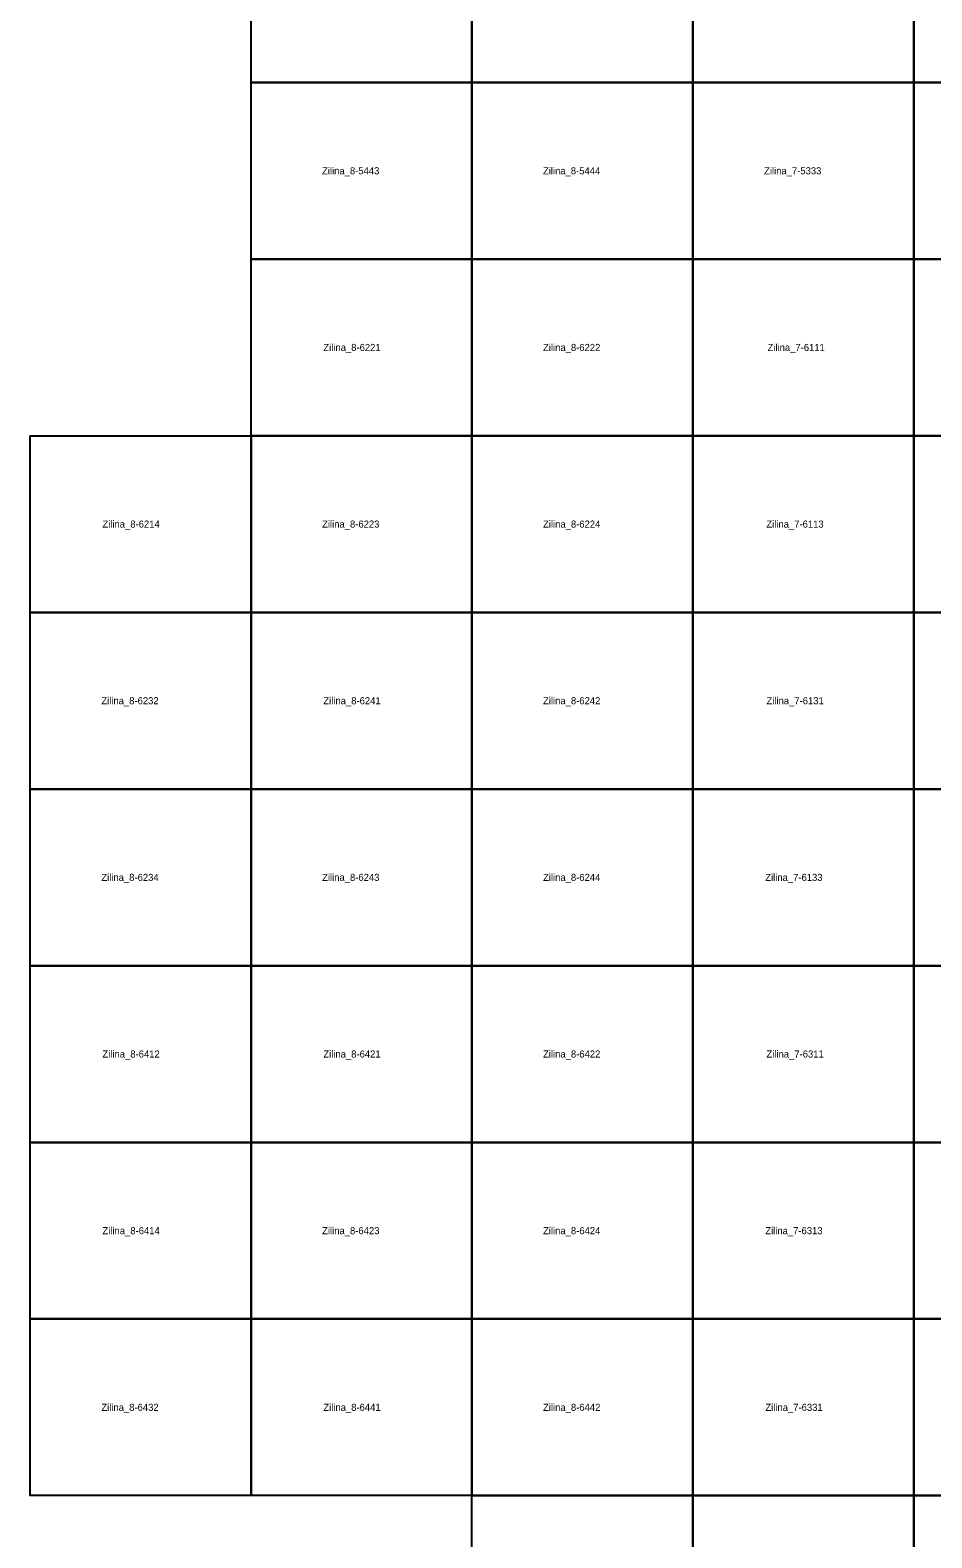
# Model space of a CAD drawing. Extents: x -445938 to -437812, y -1177250 to -1169500.
# Drawn here: x -445938 to -444662, y -1173810 to -1171676 of the extents above; entities that cross this region are included whole.
import ezdxf

# ---------------------------------------------------------------- set-up
doc = ezdxf.new("R2010")
doc.units = 0
for name, color, linetype in [('Vrstva 1', 7, 'Continuous'), ('Vrstva 4', 7, 'Continuous'), ('Vrstva 6', 7, 'Continuous')]:
    doc.layers.add(name, color=color, linetype=linetype)

msp = doc.modelspace()

# ---------------------------------------------------------------- linework, layer by layer
at = {"layer": 'Vrstva 1'}
msp.add_lwpolyline([(-440625, -1175500), (-441562.5, -1175500), (-441562.5, -1175000), (-442812.5, -1175000), (-442812.5, -1175750), (-443437.5, -1175750), (-443437.5, -1177250), (-445000, -1177250), (-445000, -1175500), (-445312.5, -1175500), (-445312.5, -1173750), (-445937.5, -1173750), (-445937.5, -1172250), (-445625, -1172250), (-445625, -1169500), (-444062.5, -1169500), (-444062.5, -1169750), (-441562.5, -1169750), (-441562.5, -1170000), (-440000, -1170000)], dxfattribs=at)
at = {"layer": 'Vrstva 4'}
for points in [[(-445312.5, -1171500), (-445312.5, -1171750), (-445625, -1171750), (-445625, -1171500)], [(-445000, -1171500), (-445000, -1171750), (-445312.5, -1171750), (-445312.5, -1171500)], [(-444687.5, -1171500), (-444687.5, -1171750), (-445000, -1171750), (-445000, -1171500)], [(-444375, -1171500), (-444375, -1171750), (-444687.5, -1171750), (-444687.5, -1171500)], [(-445312.5, -1171750), (-445312.5, -1172000), (-445625, -1172000), (-445625, -1171750)], [(-445000, -1171750), (-445000, -1172000), (-445312.5, -1172000), (-445312.5, -1171750)], [(-444687.5, -1171750), (-444687.5, -1172000), (-445000, -1172000), (-445000, -1171750)], [(-444375, -1171750), (-444375, -1172000), (-444687.5, -1172000), (-444687.5, -1171750)], [(-445312.5, -1172000), (-445312.5, -1172250), (-445625, -1172250), (-445625, -1172000)], [(-445000, -1172000), (-445000, -1172250), (-445312.5, -1172250), (-445312.5, -1172000)], [(-444687.5, -1172000), (-444687.5, -1172250), (-445000, -1172250), (-445000, -1172000)], [(-444375, -1172000), (-444375, -1172250), (-444687.5, -1172250), (-444687.5, -1172000)], [(-445625, -1172250), (-445625, -1172500), (-445937.5, -1172500), (-445937.5, -1172250)], [(-445312.5, -1172250), (-445312.5, -1172500), (-445625, -1172500), (-445625, -1172250)], [(-445000, -1172250), (-445000, -1172500), (-445312.5, -1172500), (-445312.5, -1172250)], [(-444687.5, -1172250), (-444687.5, -1172500), (-445000, -1172500), (-445000, -1172250)], [(-444375, -1172250), (-444375, -1172500), (-444687.5, -1172500), (-444687.5, -1172250)], [(-445625, -1172500), (-445625, -1172750), (-445937.5, -1172750), (-445937.5, -1172500)], [(-445312.5, -1172500), (-445312.5, -1172750), (-445625, -1172750), (-445625, -1172500)], [(-445000, -1172500), (-445000, -1172750), (-445312.5, -1172750), (-445312.5, -1172500)], [(-444687.5, -1172500), (-444687.5, -1172750), (-445000, -1172750), (-445000, -1172500)], [(-444375, -1172500), (-444375, -1172750), (-444687.5, -1172750), (-444687.5, -1172500)], [(-445625, -1172750), (-445625, -1173000), (-445937.5, -1173000), (-445937.5, -1172750)], [(-445312.5, -1172750), (-445312.5, -1173000), (-445625, -1173000), (-445625, -1172750)], [(-445000, -1172750), (-445000, -1173000), (-445312.5, -1173000), (-445312.5, -1172750)], [(-444687.5, -1172750), (-444687.5, -1173000), (-445000, -1173000), (-445000, -1172750)], [(-444375, -1172750), (-444375, -1173000), (-444687.5, -1173000), (-444687.5, -1172750)], [(-445625, -1173000), (-445625, -1173250), (-445937.5, -1173250), (-445937.5, -1173000)], [(-445312.5, -1173000), (-445312.5, -1173250), (-445625, -1173250), (-445625, -1173000)], [(-445000, -1173000), (-445000, -1173250), (-445312.5, -1173250), (-445312.5, -1173000)], [(-444687.5, -1173000), (-444687.5, -1173250), (-445000, -1173250), (-445000, -1173000)], [(-444375, -1173000), (-444375, -1173250), (-444687.5, -1173250), (-444687.5, -1173000)], [(-445625, -1173250), (-445625, -1173500), (-445937.5, -1173500), (-445937.5, -1173250)], [(-445312.5, -1173250), (-445312.5, -1173500), (-445625, -1173500), (-445625, -1173250)], [(-445000, -1173250), (-445000, -1173500), (-445312.5, -1173500), (-445312.5, -1173250)], [(-444687.5, -1173250), (-444687.5, -1173500), (-445000, -1173500), (-445000, -1173250)], [(-444375, -1173250), (-444375, -1173500), (-444687.5, -1173500), (-444687.5, -1173250)], [(-445625, -1173500), (-445625, -1173750), (-445937.5, -1173750), (-445937.5, -1173500)], [(-445312.5, -1173500), (-445312.5, -1173750), (-445625, -1173750), (-445625, -1173500)], [(-445000, -1173500), (-445000, -1173750), (-445312.5, -1173750), (-445312.5, -1173500)], [(-444687.5, -1173500), (-444687.5, -1173750), (-445000, -1173750), (-445000, -1173500)], [(-444375, -1173500), (-444375, -1173750), (-444687.5, -1173750), (-444687.5, -1173500)], [(-445000, -1173750), (-445000, -1174000), (-445312.5, -1174000), (-445312.5, -1173750)], [(-444687.5, -1173750), (-444687.5, -1174000), (-445000, -1174000), (-445000, -1173750)], [(-444375, -1173750), (-444375, -1174000), (-444687.5, -1174000), (-444687.5, -1173750)]]:
    msp.add_lwpolyline(points, close=True, dxfattribs=at)

# ---------------------------------------------------------------- texts
at = {"layer": 'Vrstva 6'}
for s, p in [('Zilina_8-5443', (-445524.572, -1171880)), ('Zilina_8-5444', (-445212.072, -1171880)), ('Zilina_7-5333', (-444899.256, -1171880)), ('Zilina_8-6221', (-445522.76, -1172130)), ('Zilina_8-6222', (-445211.954, -1172130)), ('Zilina_7-6111', (-444894.376, -1172130)), ('Zilina_8-6214', (-445835.261, -1172380)), ('Zilina_8-6223', (-445524.454, -1172380)), ('Zilina_8-6224', (-445211.954, -1172380)), ('Zilina_7-6113', (-444896.068, -1172380)), ('Zilina_8-6232', (-445836.796, -1172630)), ('Zilina_8-6241', (-445522.76, -1172630)), ('Zilina_8-6242', (-445211.954, -1172630)), ('Zilina_7-6131', (-444895.91, -1172630)), ('Zilina_8-6234', (-445836.796, -1172880)), ('Zilina_8-6243', (-445524.454, -1172880)), ('Zilina_8-6244', (-445211.954, -1172880)), ('Zilina_7-6133', (-444897.604, -1172880)), ('Zilina_8-6412', (-445835.261, -1173130)), ('Zilina_8-6421', (-445522.76, -1173130)), ('Zilina_8-6422', (-445211.954, -1173130)), ('Zilina_7-6311', (-444895.91, -1173130)), ('Zilina_8-6414', (-445835.261, -1173380)), ('Zilina_8-6423', (-445524.454, -1173380)), ('Zilina_8-6424', (-445211.954, -1173380)), ('Zilina_7-6313', (-444897.604, -1173380)), ('Zilina_8-6432', (-445836.796, -1173630)), ('Zilina_8-6441', (-445522.76, -1173630)), ('Zilina_8-6442', (-445211.954, -1173630)), ('Zilina_7-6331', (-444897.446, -1173630))]:
    msp.add_text(s, height=10, dxfattribs=at).set_placement(p)

doc.saveas('drawing.dxf')
